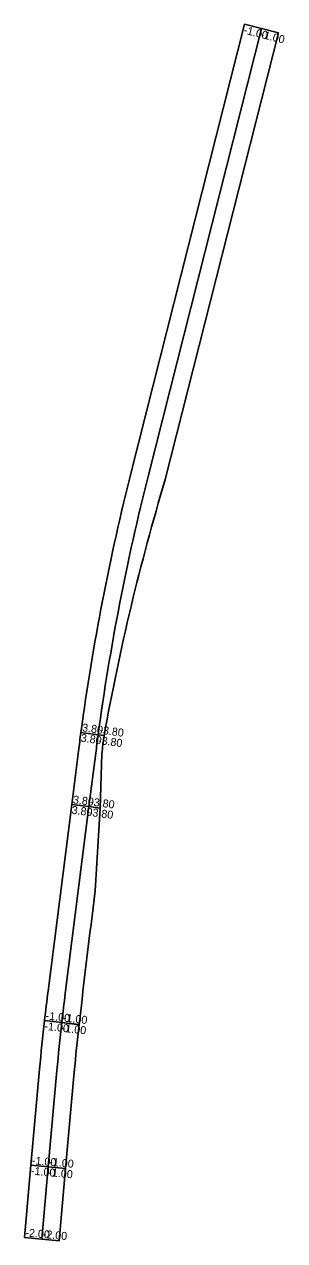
# Model space of a CAD drawing. Extents: x -200 to 1725604, y -325 to 659477.
# Drawn here: x 1725425 to 1725604, y 658638 to 659477 of the extents above; entities that cross this region are included whole.
import ezdxf

# ---------------------------------------------------------------- set-up
doc = ezdxf.new("R2010")
doc.units = 0
doc.layers.add('DESIGN - SHEET - Light Grid', color=7, linetype='Continuous')

msp = doc.modelspace()

# ---------------------------------------------------------------- linework, layer by layer
at = {"layer": 'DESIGN - SHEET - Light Grid'}
for p, q in [((1725498.38, 659168.72), (1725576.35, 659476.66)), ((1725510.02, 659165.78), (1725587.98, 659473.71)), ((1725587.98, 659473.71), (1725510.02, 659165.78)), ((1725599.61, 659470.76), (1725521.65, 659162.83)), ((1725576.35, 659476.66), (1725587.98, 659473.71)), ((1725587.98, 659473.71), (1725599.61, 659470.76)), ((1725475.42, 658986.84), (1725463.53, 658988.44)), ((1725463.53, 658988.44), (1725475.42, 658986.84)), ((1725479.55, 658986.28), (1725475.42, 658986.84)), ((1725475.42, 658986.84), (1725479.55, 658986.28)), ((1725457.18, 658938.75), (1725461.84, 658975.53)), ((1725469.09, 658937.24), (1725473.74, 658974.02)), ((1725473.74, 658974.02), (1725469.09, 658937.24)), ((1725477.9, 658973.63), (1725476.91, 658936.25)), ((1725440.87, 658809.9), (1725457.18, 658938.75)), ((1725469.09, 658937.24), (1725452.78, 658808.4)), ((1725469.09, 658937.24), (1725452.78, 658808.4)), ((1725469.09, 658937.24), (1725457.18, 658938.75)), ((1725457.18, 658938.75), (1725469.09, 658937.24)), ((1725476.91, 658936.25), (1725469.09, 658937.24)), ((1725476.91, 658936.25), (1725469.09, 658937.24)), ((1725473.38, 658879.1), (1725476.91, 658936.25)), ((1725450.38, 658788.41), (1725438.46, 658789.76)), ((1725438.46, 658789.76), (1725450.38, 658788.41)), ((1725450.38, 658788.41), (1725462.32, 658786.84)), ((1725462.31, 658787.07), (1725450.38, 658788.41)), ((1725429.05, 658689.94), (1725435.06, 658756.3)), ((1725447.01, 658755.21), (1725441, 658688.86)), ((1725447.01, 658755.21), (1725441, 658688.86)), ((1725452.95, 658687.77), (1725458.96, 658754.13)), ((1725424.54, 658640.14), (1725429.05, 658689.94)), ((1725441, 658688.86), (1725429.05, 658689.94)), ((1725429.05, 658689.94), (1725441, 658688.86)), ((1725436.5, 658639.06), (1725441, 658688.86)), ((1725441, 658688.86), (1725436.5, 658639.06)), ((1725441, 658688.86), (1725452.95, 658687.77)), ((1725441, 658688.86), (1725452.95, 658687.77)), ((1725452.95, 658687.77), (1725448.45, 658637.98)), ((1725436.5, 658639.06), (1725424.54, 658640.14)), ((1725448.45, 658637.98), (1725436.5, 658639.06))]:
    msp.add_line(p, q, dxfattribs=at)
for centre, radius, start, end in [((1727061.08, 658773.08), 1612, 165.79242, 172.32243), ((1727061.08, 658773.08), 1600, 165.79242, 172.32243), ((1727061.08, 658773.08), 1600, 165.79242, 172.32243), ((1727048.02, 658705.56), 1593.39, 163.32287, 169.85289), ((1727061.08, 658773.08), 1612, 172.32243, 172.78539), ((1727061.08, 658773.08), 1600, 172.32243, 172.78539), ((1727061.08, 658773.08), 1600, 172.32243, 172.78539), ((1726940.9, 658620.02), 1512, 172.78539, 173.55425), ((1726940.9, 658620.02), 1500, 172.78539, 173.55425), ((1726940.9, 658620.02), 1500, 172.78539, 173.55425), ((1726940.9, 658620.02), 1512, 173.55425, 174.8289), ((1726940.9, 658620.02), 1500, 173.55425, 174.8289), ((1726940.9, 658620.02), 1500, 173.55425, 174.8289), ((1726940.9, 658620.02), 1488, 173.55425, 174.8289)]:
    msp.add_arc(centre, radius, start, end, dxfattribs=at)
for centre, major_axis, ratio, start_param, end_param in [((1727044.99, 658775.25), (0, 1579.63), 0.99998, 1.436798, 1.444878), ((1732345.1, 658009.47), (6926.57, 0), 0.999717, 3.015674, 3.029093)]:
    msp.add_ellipse(centre, major_axis=major_axis, ratio=ratio, start_param=start_param, end_param=end_param, dxfattribs=at)

# ---------------------------------------------------------------- texts
for s, rotation, p in [('-1.00', 345.79242, (1725575.25, 659470.37)), ('-1.00', 345.79242, (1725586.88, 659467.43)), ('3.80', 352.32243, (1725464.12, 658989.21)), ('-3.80', 352.32243, (1725476.01, 658987.61)), ('3.80', 352.32243, (1725463.15, 658982.07)), ('-3.80', 352.32243, (1725475.05, 658980.47)), ('3.80', 352.78539, (1725457.77, 658939.52)), ('-3.80', 352.78539, (1725469.67, 658938.01)), ('3.80', 352.78539, (1725456.86, 658932.38)), ('-3.80', 352.78539, (1725468.77, 658930.87)), ('-1.00', 353.55425, (1725439.03, 658790.54)), ('-1.00', 353.55425, (1725450.96, 658789.19)), ('-1.00', 353.55425, (1725438.22, 658783.39)), ('-1.00', 353.55425, (1725450.15, 658782.04)), ('-1.00', 354.8289, (1725429.6, 658690.73)), ('-1.00', 354.8289, (1725441.56, 658689.65)), ('-1.00', 354.8289, (1725428.96, 658683.56)), ('-1.00', 354.8289, (1725440.91, 658682.48)), ('-2.00', 354.8289, (1725425.1, 658640.93)), ('-2.00', 354.8289, (1725437.05, 658639.85))]:
    msp.add_text(s, height=5.52, rotation=rotation, dxfattribs=at).set_placement(p)

doc.saveas('drawing.dxf')
